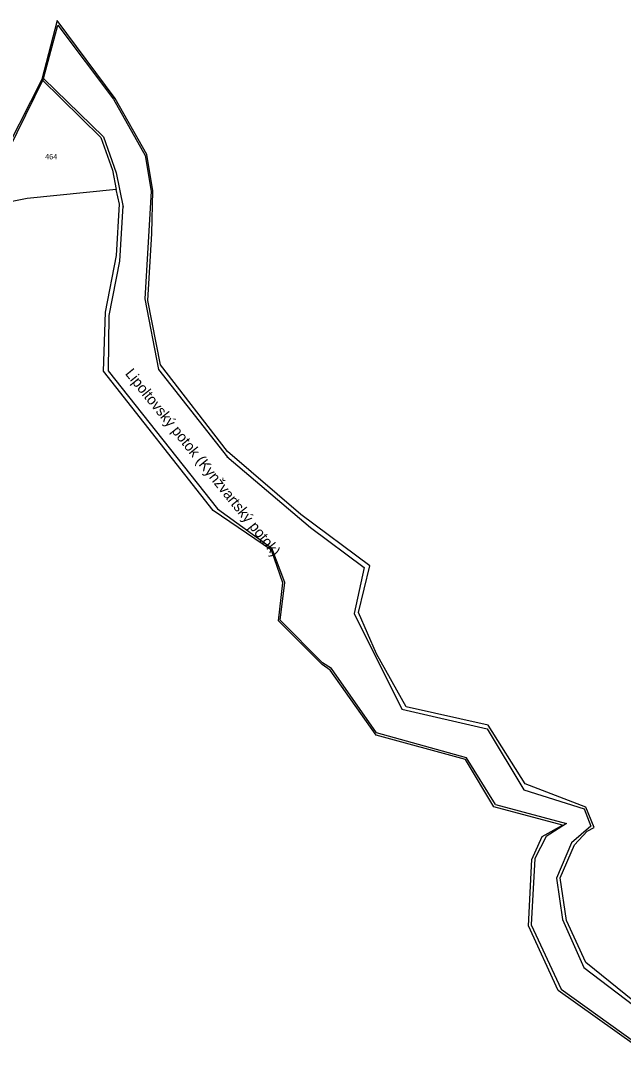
# Model space of a CAD drawing. Extents: x -880531 to -877616, y -1023932 to -1021350.
# Drawn here: x -880287.7 to -880093.6, y -1022136.1 to -1021804.2 of the extents above; entities that cross this region are included whole.
import ezdxf

# ---------------------------------------------------------------- set-up
doc = ezdxf.new("R2010")
doc.units = 0
for name, color, linetype in [('Hranice parcel', 7, 'Continuous'), ('Parcelní čísla', 7, 'Continuous'), ('Pop  PČ popisy', 7, 'Continuous'), ('Vnitřní kresba', 7, 'Continuous')]:
    doc.layers.add(name, color=color, linetype=linetype)

msp = doc.modelspace()

# ---------------------------------------------------------------- linework, layer by layer
at = {"layer": 'Hranice parcel'}
for p, q in [((-880275.96, -1021804.23), (-880280.95, -1021823.18)), ((-880245.44, -1021872.81), (-880245.16, -1021859.08)), ((-880246.78, -1021894.44), (-880245.44, -1021872.81)), ((-880242.67, -1021915.21), (-880246.78, -1021894.44)), ((-880114.03, -1022080.48), (-880109.38, -1022069.86))]:
    msp.add_line(p, q, dxfattribs=at)
for points in [[(-880245.16, -1021859.08), (-880247.07, -1021847.41), (-880257.29, -1021829.38), (-880275.96, -1021804.23)], [(-880280.95, -1021823.18), (-880295.5, -1021851.75), (-880308.92, -1021866.24)], [(-880280.95, -1021823.18), (-880261.88, -1021841.91), (-880258.1, -1021852.42), (-880256.94, -1021858.64)], [(-880256.94, -1021858.64), (-880285.61, -1021861.6), (-880308.92, -1021866.24)], [(-880085.05, -1022135.52), (-880090.05, -1022134.35), (-880114.59, -1022116.83), (-880124.2, -1022095.94), (-880123.09, -1022074.55), (-880119.83, -1022067.14), (-880113.21, -1022063.51), (-880135.34, -1022057.68), (-880144.49, -1022042.42), (-880173.19, -1022034.51), (-880188.01, -1022013.6), (-880190.67, -1022011.77), (-880204.69, -1021997.63), (-880203.31, -1021985.41), (-880206.9, -1021974.86), (-880225.75, -1021962.09), (-880261.05, -1021917.27), (-880260.44, -1021898.17), (-880256.82, -1021879.89), (-880255.85, -1021863.35), (-880256.94, -1021858.64)], [(-880197.47, -1021963.42), (-880221.14, -1021943.12), (-880242.67, -1021915.21)], [(-880173.13, -1022008.36), (-880178.94, -1021995), (-880175.27, -1021979.94), (-880197.47, -1021963.42)], [(-880103.07, -1022064.32), (-880105.7, -1022057.76), (-880125.29, -1022050.2), (-880137.12, -1022031.31), (-880163.6, -1022025.43), (-880173.13, -1022008.36)], [(-880109.38, -1022069.86), (-880105.25, -1022065.5), (-880103.07, -1022064.32)], [(-880070.63, -1022128.95), (-880075.72, -1022124.82), (-880087.84, -1022122.31), (-880105.7, -1022107.84), (-880111.94, -1022094.26), (-880114.03, -1022080.48)]]:
    msp.add_lwpolyline(points, dxfattribs=at)
at = {"layer": 'Vnitřní kresba'}
for p, q in [((-880261.07, -1021841.67), (-880280.32, -1021822.93)), ((-880257.84, -1021829.52), (-880247.61, -1021847.7)), ((-880261.07, -1021841.67), (-880257.01, -1021853.25)), ((-880257.01, -1021853.25), (-880254.71, -1021864.32)), ((-880254.8, -1021863.92), (-880255.94, -1021881.78)), ((-880255.94, -1021881.78), (-880259.34, -1021899.3)), ((-880247.69, -1021893.94), (-880243.36, -1021916.68)), ((-880259.34, -1021899.3), (-880259.59, -1021917.09)), ((-880243.36, -1021916.68), (-880221.15, -1021944.92)), ((-880259.59, -1021917.09), (-880224.34, -1021961.57)), ((-880224.34, -1021961.57), (-880206.83, -1021974.23)), ((-880180.31, -1021995.36), (-880164.99, -1022026.14)), ((-880164.99, -1022026.14), (-880137.46, -1022032.54)), ((-880137.46, -1022032.54), (-880125.66, -1022052.1)), ((-880125.66, -1022052.1), (-880106.23, -1022058.25)), ((-880134.81, -1022056.91), (-880111.97, -1022063.01)), ((-880106.23, -1022058.25), (-880104.1, -1022063.83)), ((-880111.97, -1022063.01), (-880118.45, -1022067.19)), ((-880104.1, -1022063.83), (-880110.33, -1022069.24)), ((-880118.45, -1022067.19), (-880122.13, -1022074.32)), ((-880110.33, -1022069.24), (-880115.17, -1022080.58)), ((-880115.17, -1022080.58), (-880113.21, -1022093.94)), ((-880113.21, -1022093.94), (-880106.32, -1022109.44)), ((-880106.32, -1022109.44), (-880087.55, -1022123.67))]:
    msp.add_line(p, q, dxfattribs=at)
for points in [[(-880280.32, -1021822.93), (-880275.73, -1021805.73), (-880257.84, -1021829.52)], [(-880280.32, -1021822.93), (-880294.9, -1021852.25), (-880307.77, -1021865.47), (-880316.44, -1021874.89), (-880344.91, -1021899.64), (-880361.99, -1021905.7), (-880391.18, -1021909.4), (-880413.12, -1021916.16), (-880438.71, -1021933.34), (-880463.52, -1021954.98), (-880479.1, -1021972.95), (-880517.86, -1022036.99)], [(-880247.61, -1021847.7), (-880245.68, -1021859.23), (-880247.69, -1021893.94)], [(-880221.29, -1021944.74), (-880194.41, -1021967.65), (-880177.12, -1021980.44), (-880180.31, -1021995.36)], [(-880187.6, -1022013.07), (-880190.51, -1022011.26), (-880204.14, -1021997.46), (-880202.62, -1021985.34), (-880206.83, -1021974.23)], [(-880134.81, -1022056.91), (-880144.19, -1022041.86), (-880173.13, -1022033.78), (-880187.6, -1022013.07)], [(-880122.13, -1022074.32), (-880123.37, -1022095.66), (-880113.7, -1022116.41)], [(-880113.7, -1022116.41), (-880090.09, -1022133.42), (-880075.01, -1022136.13), (-880066.24, -1022135.97), (-880057.96, -1022125.31)]]:
    msp.add_lwpolyline(points, dxfattribs=at)

# ---------------------------------------------------------------- texts
at = {"layer": 'Parcelní čísla'}
msp.add_text('464', height=1.7, dxfattribs=at).set_placement((-880279.85, -1021848.94))
at = {"layer": 'Pop  PČ popisy'}
msp.add_text('Lipoltovský potok (Kynžvartský potok)', height=3.4, rotation=309, dxfattribs=at).set_placement((-880254.247, -1021918.077))

doc.saveas('drawing.dxf')
